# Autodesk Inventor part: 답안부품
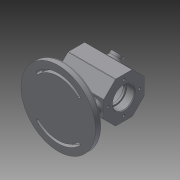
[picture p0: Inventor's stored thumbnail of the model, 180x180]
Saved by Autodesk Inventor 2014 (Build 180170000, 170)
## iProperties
Created: 2017-06
Part Number: 답안부품
Material: 일반
Document SubType Name: Modeling
Designer: net
Density: 1 g/cm^3
Appearance: 기본값
Author: net
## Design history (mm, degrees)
sketch "스케치1" dims "d0" = 60
  geometry: L1 (30, -12.426)-(12.426, -30); L2 (12.426, -30)-(-12.426, -30); L3 (-12.426, -30)-(-30, -12.426); L4 (-30, -12.426)-(-30, 12.426); L5 (-30, 12.426)-(-12.426, 30); L6 (-12.426, 30)-(12.426, 30); L7 (12.426, 30)-(30, 12.426); L8 (30, 12.426)-(30, -12.426); 4 further points
  constraints: 16 end point, 2 coincident, 2 horizontal alignment, 1 midpoint, 19 other
extrude "돌출1" new body sketch "스케치1" stored distance "d1" = 70; taper "d2" = 0 deg
sketch "스케치2"
  geometry: L1 (-35, -30)-(-35, 30) reference; L2 (-35, 30)-(35, 30) reference; L3 (35, 30)-(35, -30) reference; L4 (35, -30)-(-35, -30) reference; L5 (-35, 0)-(35, 0); L6 (35, 0)-(35, 16); L7 (35, 16)-(23.3, 16); L8 (23, 15.7)-(23, 14); L9 (23, 14)-(20, 14); L10 (20, 14)-(20, 22); L11 (17, 25)-(-17, 25); L12 (-20, 22)-(-20, 14); L13 (-20, 14)-(-23, 14); L14 (-23, 14)-(-23, 15.7); L15 (-23.3, 16)-(-35, 16); L16 (-35, 0)-(-35, 16); A1 r 0.3 centre (-23.3, 15.7) between (-23, 15.7) and (-23.3, 16); A2 r 0.3 centre (23.3, 15.7) between (23.3, 16) and (23, 15.7); A3 r 3 centre (17, 22) between (20, 22) and (17, 25); A4 r 3 centre (-17, 22) between (-17, 25) and (-20, 22); 6 further points
  constraints: 24 end point, 8 point on circle, 8 point on line, 8 tangent, 5 parallel, 4 centre point, 4 midpoint, 4 perpendicular, 2 equal radius, 1 collinear, 1 vertical alignment
  dimensions: "d3" = 12 distance of L6.end point (23, 16); "d4" = 32 diameter of L7 L5; "d5" = 28 diameter of L9 L5; "d6" = 50 diameter of L11 L5; "d7" = 32 diameter of L15 L5; "d8" = 28 diameter of L13 L5; "d9" = 40 distance of point (20, 25) point (-20, 25); "d10" = 3 distance of L12.end L13.end; "d11" = 0.3 radius of A1; "d12" = 3 radius of A3
revolve "회전1" sketch "스케치2" stored, may be unused: angle "d13" = 90 deg
chamfer "모따기1" distance "d14" = 1; stored, may be unused: second distance "d15" = 2, angle "d16" = 45 deg
sketch "스케치3" dims "d17" = 46
  geometry: C1 r 17 at (0, 0) reference; 2 further points
  constraints: 2 horizontal alignment, 1 coincident, 2 other
hole "구멍1" sketch "스케치3" at (23, 0) diameter "d18" = 3.459; stored, may be unused: countersink angle "d22" = 90 deg, drill point angle "d24" = 118 deg; dims "d19" = 8, "d20" = 4, "d21" = 2, "d23" = 10
sketch "스케치4" dims "d28" = 46
  geometry: C1 r 17 at (0, 0) reference; 2 further points
  constraints: 2 horizontal alignment, 1 coincident, 2 other
hole "구멍2" sketch "스케치4" at (23, 0) diameter "d29" = 3.459; stored, may be unused: countersink angle "d33" = 90 deg, drill point angle "d35" = 118 deg; dims "d30" = 8, "d31" = 4, "d32" = 2, "d34" = 10
node "작업 평면1"
sketch "스케치5"
  geometry: C1 r 55 at (0, 0); 1 further point
  constraints: 1 centre point, 1 coincident
  dimensions: "d40" = 110 diameter of C1
extrude "돌출2" join sketch "스케치5" distance "d41" = 10; taper "d42" = 0 deg
fillet "모깎기1" dims "d43" = 3
sketch "스케치6"
  geometry: L1 (-24, 0)-(24, 0); L2 (-24, -5)-(24, -5); L3 (24, 5)-(-24, 5); C1 r 52 at (0, 0) reference; A1 r 5 centre (-24, 0) between (-24, 5) and (-24, -5); A2 r 5 centre (24, 0) between (24, -5) and (24, 5); 1 further point
  constraints: 8 end point, 4 point on circle, 4 tangent, 2 centre point, 2 coincident, 1 horizontal, 1 midpoint, 1 parallel
  dimensions: "d44" = 48 distance of L1.end L1.start; "d45" = 5 radius of A2
extrude "돌출3" join sketch "스케치6" stored distance "d46" = 10; taper "d47" = 0 deg
fillet "모깎기2" dims "d48" = 5
sketch "스케치7"
  geometry: L1 (-24, -10)-(24, -10) reference; L2 (0, 0)-(41.498, 41.498); L3 (0, 0)-(0, 67.736); L4 (0, 0)-(-48.779, 48.779); C1 r 52 at (0, 0) reference; A1 r 38 centre (0, 0) between (26.87, 26.87) and (-26.87, 26.87); A2 r 48 centre (0, 0) between (33.941, 33.941) and (-33.941, 33.941); A3 r 43 centre (0, 0) between (33.73, 26.67) and (-33.73, 26.67); A4 r 5 centre (30.406, 30.406) between (33.941, 33.941) and (33.73, 26.67); A5 r 5 centre (-30.406, 30.406) between (-33.941, 33.941) and (-33.73, 26.67)
  constraints: 14 point on circle, 6 end point, 5 centre point, 3 coincident, 2 point on line, 1 perpendicular
  dimensions: "d49" = 76 diameter of A1; "d50" = 96 diameter of A2; "d51" = 86 diameter of A3; "d52" = 45 deg angle of L2 L3; "d53" = 45 deg angle of L3 L4
extrude "돌출4" cut sketch "스케치7" distance "d54" = 3; taper "d55" = 0 deg
sketch "스케치8"
  geometry: A1 r 5 centre (-30.406, 30.406) between (-33.941, 33.941) and (-26.87, 26.87) reference; A2 r 38 centre (0, 0) between (26.87, 26.87) and (-26.87, 26.87) reference; A3 r 5 centre (30.406, 30.406) between (26.87, 26.87) and (33.941, 33.941) reference; A4 r 48 centre (0, 0) between (33.941, 33.941) and (-33.941, 33.941) reference; A5 r 2 centre (30.406, 30.406) between (31.82, 31.82) and (31.787, 28.959); A6 r 2 centre (-30.406, 30.406) between (-31.82, 31.82) and (-31.787, 28.959); A7 r 41 centre (0, 0) between (28.991, 28.991) and (-28.991, 28.991); A8 r 45 centre (0, 0) between (31.82, 31.82) and (-31.82, 31.82); A9 r 43 centre (0, 0) between (31.787, 28.959) and (-31.787, 28.959); 2 further points
  constraints: 14 point on circle, 5 centre point, 5 coincident, 2 vertical alignment
  dimensions: "d57" = 4 diameter of A5; "d58" = 4 diameter of A6; "d61" = 82 diameter of A7
extrude "돌출5" cut sketch "스케치8" stored distance "d62" = 3; taper "d63" = 0 deg
fillet "모깎기3" dims "d64" = 1
fillet "모깎기4" dims "d65" = 1
sketch "스케치9"
  geometry: L1 (0, 0.707)-(0, 17.695) reference; L2 (70, 17.988)-(0, 17.988) reference; 2 further points
  constraints: 1 other
  dimensions: "d66" = 35 distance from line of point (35, -12.012) L1; "d67" = 30 distance from line of point (35, -12.012) L2
feature "엠보싱1" sketch "스케치9" dims "d3" = 12, "d4" = 32, "d5" = 28, "d6" = 50, "d7" = 32, "d8" = 28, "d9" = 40, "d10" = 3, "d11" = 0.3, "d12" = 3, "d68" = 0.5, "d69" = 0
sketch "스케치10"
  geometry: L1 (-52, 48)-(-55, 48) reference; L2 (-55, 48)-(-55, 45) reference; L3 (-55, 45)-(-62, 45) reference; L4 (-62, 45)-(-62, 55) reference; L5 (-62, 55)-(-55, 55) reference; L6 (-52, 52)-(-52, 48) reference; L7 (-55, -48)-(-52, -48) reference; L8 (-52, -48)-(-52, -52) reference; L9 (-55, -55)-(-62, -55) reference; L10 (-62, -55)-(-62, -45) reference; L11 (-62, -45)-(-55, -45) reference; L12 (-55, -45)-(-55, -48) reference; L13 (-47, 5)-(-35, 5) reference; L14 (-30, 10)-(-30, 12.012) reference; L15 (-29.707, 12.719)-(-12.719, 29.707) reference; L16 (-12.012, 30)-(12.012, 30) reference; L17 (12.719, 29.707)-(29.707, 12.719) reference; L18 (30, 12.012)-(30, -2.365) reference; L19 (30, -2.365)-(30.5, -2.365) reference; L20 (30.5, -2.365)-(30.5, -2.862) reference; L21 (30.5, -2.862)-(30, -2.862) reference; L22 (30, -2.862)-(30, -12.012) reference; L23 (29.707, -12.719)-(12.719, -29.707) reference; L24 (12.012, -30)-(-12.012, -30) reference; L25 (-12.719, -29.707)-(-29.707, -12.719) reference; L26 (-30, -12.012)-(-30, -10) reference; L27 (-35, -5)-(-47, -5) reference; L28 (-52, -10)-(-52, -38) reference; L29 (-52, -38)-(-55, -38) reference; L30 (-55, -38)-(-55, -41) reference; L31 (-55, -41)-(-62, -41) reference; L32 (-62, -41)-(-62, 41) reference; L33 (-62, 41)-(-55, 41) reference; L34 (-55, 41)-(-55, 38) reference; L35 (-55, 38)-(-52, 38) reference; L36 (-52, 38)-(-52, 10) reference; L37 (0, 0)-(37.213, 0); L38 (0, 0)-(26.163, 26.163); C1 r 25 at (0, 0) reference; A1 r 3 centre (-55, 52) between (-52, 52) and (-55, 55) reference; A2 r 3 centre (-55, -52) between (-55, -55) and (-52, -52) reference; A3 r 5 centre (-47, 10) between (-52, 10) and (-47, 5) reference; A4 r 5 centre (-35, 10) between (-35, 5) and (-30, 10) reference; A5 r 1 centre (-29, 12.012) between (-29.707, 12.719) and (-30, 12.012) reference; A6 r 1 centre (-12.012, 29) between (-12.012, 30) and (-12.719, 29.707) reference; A7 r 1 centre (12.012, 29) between (12.719, 29.707) and (12.012, 30) reference; A8 r 1 centre (29, 12.012) between (30, 12.012) and (29.707, 12.719) reference; A9 r 1 centre (29, -12.012) between (29.707, -12.719) and (30, -12.012) reference; A10 r 1 centre (12.012, -29) between (12.012, -30) and (12.719, -29.707) reference; A11 r 1 centre (-12.012, -29) between (-12.719, -29.707) and (-12.012, -30) reference; A12 r 1 centre (-29, -12.012) between (-30, -12.012) and (-29.707, -12.719) reference; A13 r 5 centre (-35, -10) between (-30, -10) and (-35, -5) reference; A14 r 5 centre (-47, -10) between (-47, -5) and (-52, -10) reference; 1 further point
  constraints: 4 end point, 1 perpendicular
  dimensions: "d72" = 37 distance of L37.start L38.end; "d73" = 45 deg angle of L37 L38
  node "절단 모서리 투영2"
node "작업 평면2"
sketch "스케치11"
  geometry: C1 r 8 at (0, 0); 1 further point
  constraints: 1 centre point, 1 coincident
  dimensions: "d74" = 16 diameter of C1
extrude "돌출6" join sketch "스케치11" stored distance "d75" = 3; taper "d76" = 0 deg
sketch "스케치12"
  geometry: C1 r 8 at (0, 0) reference; C2 r 4 at (0, 0)
  constraints: 1 centre point, 1 coincident
  dimensions: "d77" = 8 diameter of C2
extrude "돌출7" cut sketch "스케치12" stored distance "d78" = 3; taper "d79" = 0 deg
fillet "모깎기5" dims "d80" = 3
chamfer "모따기2" distance "d81" = 1; stored, may be unused: second distance "d82" = 2, angle "d83" = 45 deg
node "솔리드1"
pattern_circular "원형 패턴1" dims angle "d26" = 360 deg
pattern_circular "원형 패턴2" dims angle "d37" = 360 deg
mirror "대칭1"
node "절단 모서리 투영1"
other parameters: "d39" = -62, "d56" = 86
